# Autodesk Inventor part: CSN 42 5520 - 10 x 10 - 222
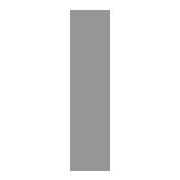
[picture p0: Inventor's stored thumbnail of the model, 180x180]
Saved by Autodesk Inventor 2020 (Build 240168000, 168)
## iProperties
Created: 2019-01
Part Number: CSN 42 5520 - 10 x 10 - 222
Material: Ocel, měkká
Description: Tyč
Document SubType Name: Modeling
Standard: CSN 42 5520
Designer: doma
Standards Organization: CSN
Language: cs-CZ
Size Designation: 10 x 10 - 222
Categories: <MemberInstance><Categories><Category DisplayName="Konstrukční profily" InternalName="089c4875-fa83-4c05-b084-43b9cc11f5ed" Mnemonic="GRDR"><CategoryParameter D
Stock Number: 10 x 10
Density: 7.85 g/cm^3
Appearance: Pololeštěná
Mass: 173.044 g
Surface Area: 91.049 cm^2
Volume: 22.0438 cm^3
IsCustomPart: 1
G_L: 222,000 mm
Author: doma
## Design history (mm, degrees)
node "Počáteční rovina"
node "Koncová rovina"
sketch "Náčrt"
  geometry: L1 (5, -5)-(-5, -5); L2 (-5, -5)-(-5, 5); L3 (-5, 5)-(5, 5); L4 (5, 5)-(5, -5); L5 (-6, 0)-(8, 0); L6 (0, -30)-(0, 40); L7 (0, 54)-(0, -44) reference; L8 (-9.2, 0)-(13.2, 0) reference
  constraints: 12 end point, 2 collinear, 2 parallel, 1 horizontal, 1 perpendicular
  dimensions: "d0" = 10 distance between parallel lines of L3 L1 (= G_W); "d1" = 10 distance between parallel lines of L4 L2 (= G_H); "d4" = 5 distance between parallel lines of L6 L4 (= 0.5 x d1); "d5" = 5 distance between parallel lines of L5 L3 (= 0.5 x d0)
extrude "Těleso" new body sketch "Náčrt" stored distance "d2" = 228; taper "d3" = 0 deg
node "Driven Length"
  sketch "Sketch3"
    geometry: L1 (0, 0)-(10, 0) reference
    constraints: 2 end point, 1 horizontal
  workplane "Work Plane3"
  sketch "Sketch4"
    geometry: L1 (-2, 0)-(12, 0) reference; L2 (-2, 222)-(12, 222) reference
    dimensions: "d9" = 222 distance between parallel lines of L1 L2 (derived)
sketch "Náčrt5"
  geometry: L1 (10, 5.942)-(3.025, 0) reference; L2 (1.523, 227.664)-(10, 224.862) reference; L3 (1.523, 227.664)-(-7.126, 230.521); L4 (-7.126, 230.521)-(-4.478, 238.534); L5 (-4.478, 238.534)-(23.877, 231.045); L6 (23.877, 231.045)-(10, 224.862); L7 (0, 228)-(0, 0) reference; L8 (0, 20)-(2, 20); L9 (2, 20)-(2, 0); L10 (10, 0)-(0, 0) reference; L11 (10, 0)-(10, 228) reference; C1 r 64 at (-63.481, 5.692) reference; 1 further point
  constraints: 12 end point, 2 perpendicular, 2 point on line, 1 horizontal
  dimensions: "d10" = 20 distance of L9.end L8.end; "d11" = 8 distance between parallel lines of L11 L9
extrude "Vysunutí2" cut sketch "Náčrt5" distance "d12" = 228; taper "d13" = 0 deg
chamfer "Zkosení1" distance "d14" = 2; stored, may be unused: second distance "d15" = 2, angle "d16" = 45 deg
body "Solid1"
node "Referenční1"
node "Referenční2"
node "Referenční3"
other parameters: "G_W" = 10 [user parameter; used in 1 equation term], "G_H" = 10 [user parameter; used in 1 equation term], "G_L" = 222 (= d9) [user parameter], "G_OFFSET_START" = 0 [user parameter; used in 1 equation term], "G_OFFSET_END" = 0 [user parameter; used in 1 equation term], "d6" = 0 (computed from G_OFFSET_START), "d7" = 222 (= G_OFFSET_END + B_L), "B_L" = 222 [user parameter; used in 1 equation term], "d8" = 90 deg
